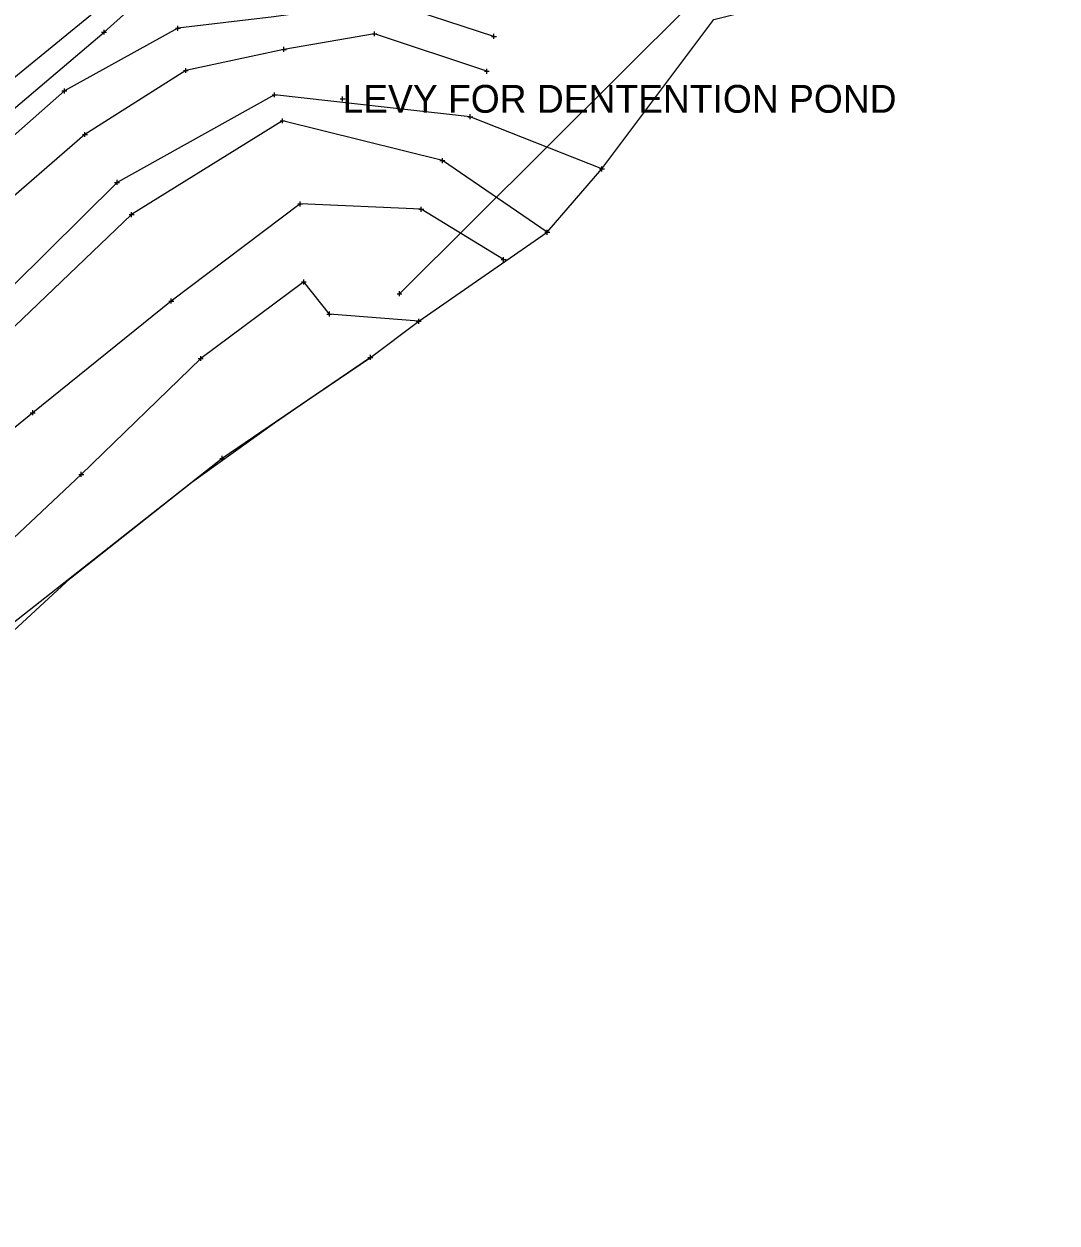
# Model space of a CAD drawing. Extents: x -1 to 1157254, y -1 to 2021979.
# Drawn here: x 1149538.4 to 1149805.7, y 2018669.7 to 2018979.9 of the extents above; entities that cross this region are included whole.
import ezdxf

# ---------------------------------------------------------------- set-up
doc = ezdxf.new("R2010")
doc.units = 0
for name, color, linetype in [('S_BUILDING_ANNOT', 7, 'Continuous'), ('S_CTL_TABLE', 7, 'Continuous'), ('S_DRIVEWAY_ANNOT', 7, 'Continuous'), ('S_DROP_INLET_ANNOT', 7, 'Continuous'), ('S_EDGE_BITUMINOUS_ANNOT', 7, 'Continuous'), ('S_EXIST_ROW_ANNOT', 7, 'Continuous'), ('S_GAS_PUMP_ISLAND_ANNOT', 7, 'Continuous'), ('S_GATE', 7, 'Continuous')]:
    doc.layers.add(name, color=color, linetype=linetype)

msp = doc.modelspace()

# ---------------------------------------------------------------- linework, layer by layer
at = {"layer": 'S_BUILDING_ANNOT'}
for p, q in [((1149558.47, 2018977.73), (1149559.74, 2018977.74)), ((1149559.1, 2018977.1), (1149559.1, 2018978.37)), ((1149559.1, 2018977.73), (1149559.1, 2018977.73)), ((1149602.59, 2018961.52), (1149603.86, 2018961.52)), ((1149603.23, 2018960.88), (1149603.23, 2018962.16)), ((1149603.23, 2018961.52), (1149603.23, 2018961.52)), ((1149620.21, 2018960.49), (1149621.48, 2018960.49)), ((1149620.84, 2018959.86), (1149620.84, 2018961.13)), ((1149620.84, 2018960.49), (1149620.84, 2018960.49)), ((1149604.69, 2018954.8), (1149605.96, 2018954.8)), ((1149605.33, 2018954.16), (1149605.33, 2018955.43)), ((1149605.33, 2018954.8), (1149605.33, 2018954.8)), ((1149653.27, 2018955.87), (1149654.54, 2018955.87)), ((1149653.9, 2018955.23), (1149653.9, 2018956.5)), ((1149653.9, 2018955.87), (1149653.9, 2018955.87)), ((1149646.68, 2018943.88), (1149646.68, 2018945.15)), ((1149646.04, 2018944.52), (1149647.31, 2018944.52)), ((1149646.68, 2018944.52), (1149646.68, 2018944.52)), ((1149687.32, 2018942.37), (1149688.59, 2018942.37)), ((1149687.96, 2018941.73), (1149687.95, 2018943.01)), ((1149687.95, 2018942.37), (1149687.95, 2018942.37)), ((1149561.86, 2018938.88), (1149563.13, 2018938.88)), ((1149562.49, 2018938.24), (1149562.49, 2018939.52)), ((1149562.49, 2018938.88), (1149562.49, 2018938.88)), ((1149565.6, 2018930.53), (1149566.87, 2018930.53)), ((1149566.24, 2018929.9), (1149566.23, 2018931.17)), ((1149566.24, 2018930.53), (1149566.24, 2018930.53)), ((1149673.82, 2018925.34), (1149673.82, 2018926.62)), ((1149673.19, 2018925.98), (1149674.46, 2018925.98)), ((1149673.82, 2018925.98), (1149673.82, 2018925.98)), ((1149610.17, 2018913.14), (1149611.44, 2018913.14)), ((1149610.81, 2018912.5), (1149610.8, 2018913.78)), ((1149610.8, 2018913.14), (1149610.8, 2018913.14)), ((1149634.93, 2018910.08), (1149636.2, 2018910.08)), ((1149635.57, 2018909.44), (1149635.57, 2018910.72)), ((1149635.57, 2018910.08), (1149635.57, 2018910.08)), ((1149616.79, 2018904.81), (1149618.06, 2018904.81)), ((1149617.43, 2018904.17), (1149617.42, 2018905.45)), ((1149617.43, 2018904.81), (1149617.43, 2018904.81)), ((1149639.93, 2018902.96), (1149641.2, 2018902.96)), ((1149640.57, 2018902.32), (1149640.56, 2018903.6)), ((1149640.56, 2018902.96), (1149640.56, 2018902.96)), ((1149583.5, 2018893.32), (1149584.78, 2018893.33)), ((1149584.14, 2018892.69), (1149584.14, 2018893.96)), ((1149584.14, 2018893.32), (1149584.14, 2018893.32)), ((1149552.58, 2018863.33), (1149553.85, 2018863.33)), ((1149553.22, 2018862.69), (1149553.21, 2018863.96)), ((1149553.21, 2018863.33), (1149553.21, 2018863.33))]:
    msp.add_line(p, q, dxfattribs=at)
at = {"layer": 'S_CTL_TABLE'}
for p, q in [((1149578.25, 2018978.09), (1149578.25, 2018979.37)), ((1149577.61, 2018978.73), (1149578.88, 2018978.73)), ((1149578.25, 2018978.73), (1149578.25, 2018978.73)), ((1149628.46, 2018977.29), (1149629.74, 2018977.29)), ((1149629.1, 2018976.66), (1149629.1, 2018977.93)), ((1149629.1, 2018977.29), (1149629.1, 2018977.29)), ((1149659.39, 2018976.65), (1149660.66, 2018976.65)), ((1149660.03, 2018976.01), (1149660.03, 2018977.29)), ((1149660.03, 2018976.65), (1149660.03, 2018976.65)), ((1149605.05, 2018973.28), (1149606.32, 2018973.28)), ((1149605.68, 2018972.65), (1149605.68, 2018973.92)), ((1149605.68, 2018973.28), (1149605.68, 2018973.28)), ((1149579.65, 2018967.82), (1149580.92, 2018967.82)), ((1149580.28, 2018967.18), (1149580.28, 2018968.45)), ((1149580.28, 2018967.82), (1149580.28, 2018967.82)), ((1149657.53, 2018967.63), (1149658.8, 2018967.63)), ((1149658.17, 2018966.99), (1149658.16, 2018968.27)), ((1149658.16, 2018967.63), (1149658.16, 2018967.63)), ((1149548.23, 2018962.54), (1149549.5, 2018962.54)), ((1149548.87, 2018961.9), (1149548.87, 2018963.17)), ((1149548.87, 2018962.54), (1149548.87, 2018962.54)), ((1149553.52, 2018951.26), (1149554.79, 2018951.27)), ((1149554.16, 2018950.63), (1149554.15, 2018951.9)), ((1149554.15, 2018951.27), (1149554.15, 2018951.27)), ((1149609.24, 2018933.32), (1149610.51, 2018933.32)), ((1149609.88, 2018932.68), (1149609.88, 2018933.95)), ((1149609.88, 2018933.32), (1149609.88, 2018933.32)), ((1149641.21, 2018931.27), (1149641.21, 2018932.54)), ((1149640.58, 2018931.91), (1149641.85, 2018931.91)), ((1149641.21, 2018931.91), (1149641.21, 2018931.91)), ((1149661.88, 2018918.91), (1149663.15, 2018918.91)), ((1149662.51, 2018918.28), (1149662.51, 2018919.55)), ((1149662.51, 2018918.91), (1149662.51, 2018918.91)), ((1149575.86, 2018908.16), (1149577.13, 2018908.16)), ((1149576.5, 2018907.52), (1149576.49, 2018908.8)), ((1149576.49, 2018908.16), (1149576.49, 2018908.16)), ((1149627.39, 2018893.59), (1149628.67, 2018893.59)), ((1149628.03, 2018892.96), (1149628.03, 2018894.23)), ((1149628.03, 2018893.59), (1149628.03, 2018893.59)), ((1149540.66, 2018878.65), (1149540.66, 2018879.92)), ((1149540.02, 2018879.28), (1149541.3, 2018879.28)), ((1149540.66, 2018879.28), (1149540.66, 2018879.28)), ((1149589.04, 2018867.47), (1149590.31, 2018867.48)), ((1149589.68, 2018866.84), (1149589.67, 2018868.11)), ((1149589.67, 2018867.47), (1149589.67, 2018867.47))]:
    msp.add_line(p, q, dxfattribs=at)
at = {"layer": 'S_DRIVEWAY_ANNOT'}
for points in [[(1149376.61, 2018808.08), (1149378.14, 2018810.98), (1149389.01, 2018823.67), (1149409.46, 2018847.56), (1149440.18, 2018874.39), (1149475.97, 2018908.75), (1149505.19, 2018937.2), (1149526.69, 2018958.59), (1149556.52, 2018982.92), (1149580.72, 2019006.3), (1149603.46, 2019020.75), (1149621.36, 2019031.87)], [(1149376.44, 2018806.04), (1149380.49, 2018808.15), (1149394.25, 2018816.7), (1149415.4, 2018840.88), (1149444.35, 2018868.67), (1149479.15, 2018904.69), (1149508.95, 2018932.79), (1149529.9, 2018953.01), (1149559.1, 2018977.73), (1149584.9, 2019000.96), (1149605.2, 2019016.88), (1149625.32, 2019028.84)], [(1149640.56, 2018902.96), (1149617.43, 2018904.81), (1149610.8, 2018913.14), (1149584.14, 2018893.32), (1149553.21, 2018863.33), (1149526.84, 2018838.61), (1149488.79, 2018806.84), (1149449.77, 2018773.73), (1149420.5, 2018750.84), (1149425.23, 2018735.84), (1149451.25, 2018712.44), (1149456.98, 2018700.1), (1149457.92, 2018696.52)]]:
    msp.add_lwpolyline(points, dxfattribs=at)
at = {"layer": 'S_DROP_INLET_ANNOT'}
msp.add_lwpolyline([(1149711.3, 2018985.38), (1149635.57, 2018910.08)], dxfattribs=at)
at = {"layer": 'S_EDGE_BITUMINOUS_ANNOT'}
for points in [[(1149660.03, 2018976.65), (1149631.99, 2018985.75), (1149603.08, 2018981.73), (1149578.25, 2018978.73), (1149548.87, 2018962.54), (1149520.83, 2018937.94), (1149489.35, 2018908.4), (1149463.06, 2018881.32), (1149437.76, 2018856.18), (1149412.61, 2018831.09), (1149389.75, 2018805.71)], [(1149658.16, 2018967.63), (1149629.1, 2018977.29), (1149605.68, 2018973.28), (1149580.28, 2018967.82), (1149554.15, 2018951.27), (1149527.17, 2018927.9), (1149498.99, 2018899.71), (1149468.02, 2018871.41), (1149443.75, 2018849.24), (1149417.05, 2018823.84), (1149394.92, 2018799.71)], [(1149662.51, 2018918.91), (1149641.21, 2018931.91), (1149609.88, 2018933.32), (1149576.49, 2018908.16), (1149540.66, 2018879.28), (1149514.46, 2018858), (1149478.76, 2018821.19), (1149437.7, 2018789.45), (1149404.32, 2018757.49), (1149403.89, 2018735.24), (1149450.02, 2018684.14)], [(1149628.03, 2018893.59), (1149589.67, 2018867.47), (1149535.72, 2018824.97), (1149497.88, 2018784.73), (1149462.39, 2018746.85), (1149444.79, 2018729.63)]]:
    msp.add_lwpolyline(points, dxfattribs=at)
at = {"layer": 'S_EXIST_ROW_ANNOT'}
for points in [[(1149687.95, 2018942.37), (1149653.9, 2018955.87), (1149603.23, 2018961.52), (1149562.49, 2018938.88), (1149526.26, 2018903.04), (1149498.23, 2018881.1), (1149458.63, 2018846.1), (1149419.57, 2018813.34), (1149387.83, 2018776.41), (1149372.07, 2018764.27)], [(1149673.82, 2018925.98), (1149646.68, 2018944.52), (1149605.33, 2018954.8), (1149566.24, 2018930.53), (1149529.93, 2018895.93), (1149503.49, 2018871.44), (1149465.25, 2018838.56), (1149425.49, 2018806.53), (1149384.95, 2018765.42), (1149386.43, 2018735.51), (1149441.66, 2018669.67)]]:
    msp.add_lwpolyline(points, dxfattribs=at)
at = {"layer": 'S_GAS_PUMP_ISLAND_ANNOT'}
msp.add_lwpolyline([(1149522.02, 2018810.4), (1149550.4, 2018836.53), (1149558.25, 2018842.72), (1149566.11, 2018848.91), (1149573.96, 2018855.1), (1149581.82, 2018861.29), (1149603.24, 2018876.71), (1149611.5, 2018882.34), (1149619.77, 2018887.97), (1149628.03, 2018893.59), (1149640.56, 2018902.96), (1149673.82, 2018925.98), (1149687.95, 2018942.37), (1149716.91, 2018980.98), (1149726.6, 2018983.4), (1149732.54, 2018984.88), (1149778.18, 2019000.24), (1149787.56, 2019003.64), (1149833.5, 2019010.84)], dxfattribs=at)

# ---------------------------------------------------------------- texts
at = {"layer": 'S_GATE'}
msp.add_text('LEVY FOR DENTENTION POND', height=7.2, dxfattribs=at).set_placement((1149620.84, 2018956.89))

doc.saveas('drawing.dxf')
